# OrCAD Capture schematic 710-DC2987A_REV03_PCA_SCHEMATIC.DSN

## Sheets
1 PAGE 2
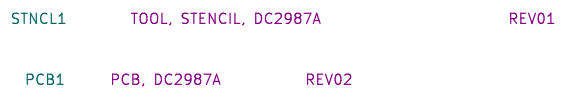
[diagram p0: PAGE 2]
2 LT3935JV: size Custom; company: 36V, 4A SYNCHRONOUS BUCK LED DRIVER
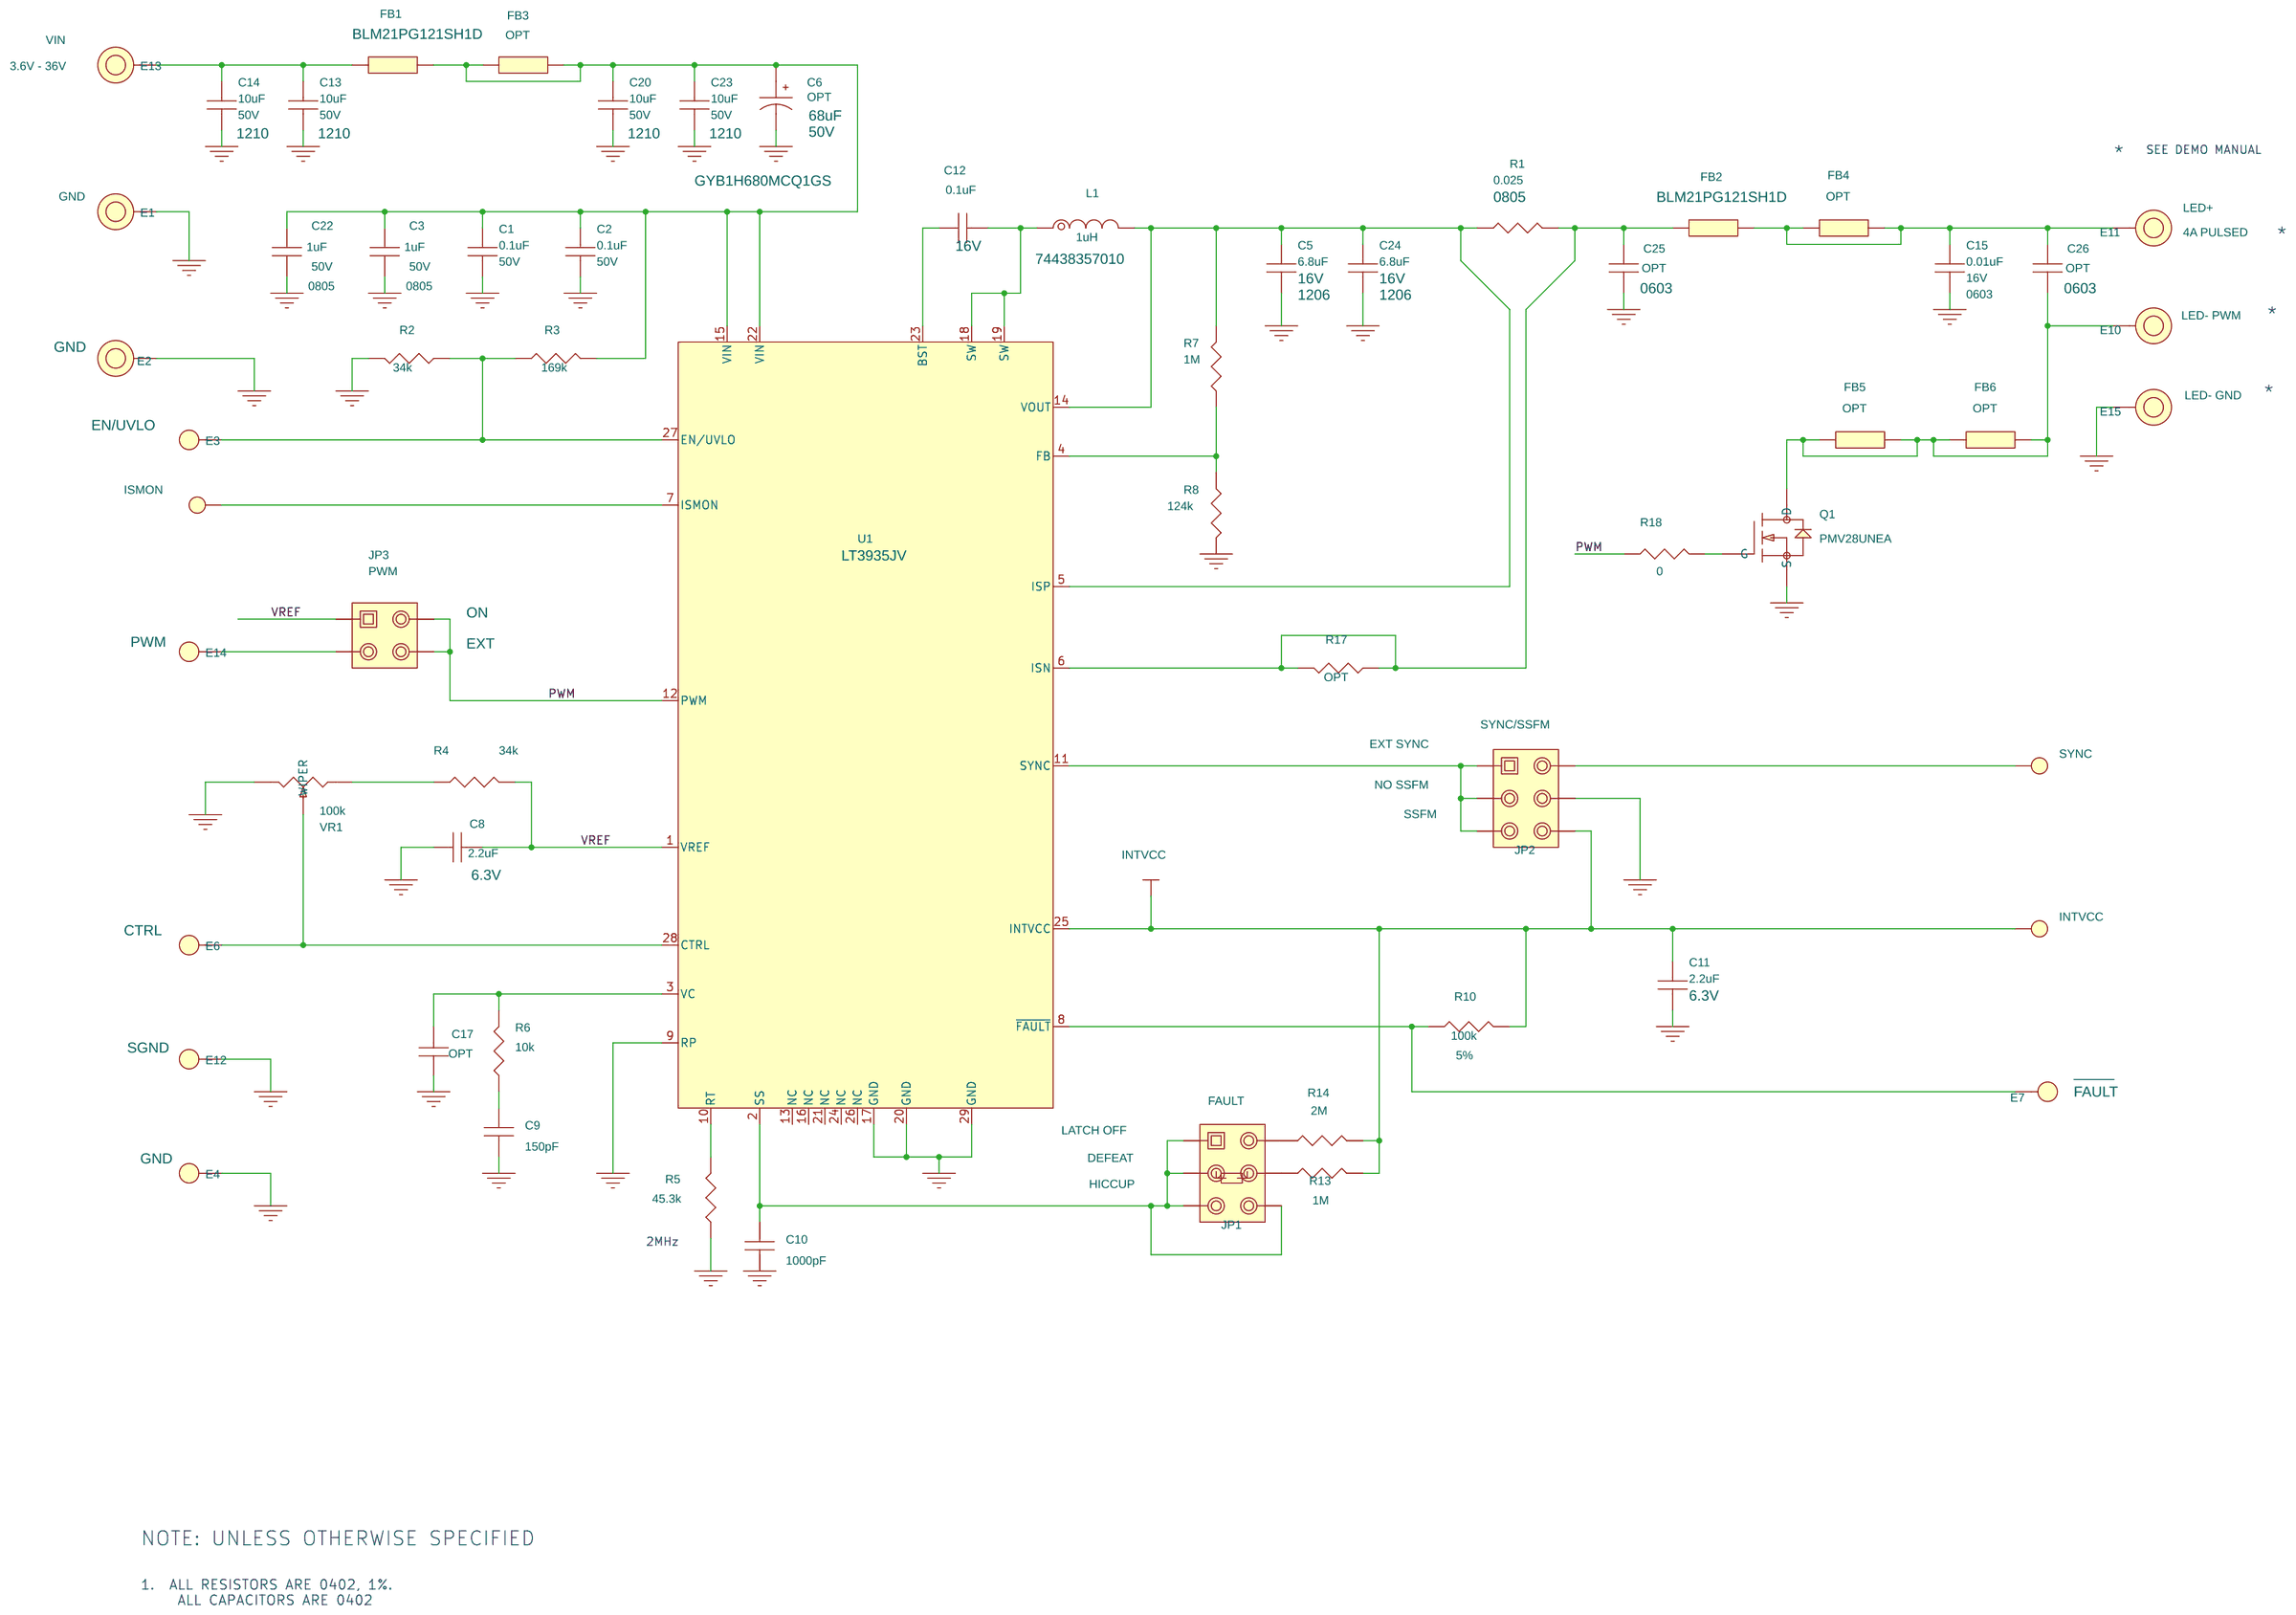
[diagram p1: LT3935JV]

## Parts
sheet LT3935JV
C1  0.1uF  [CC0402N]
C2  0.1uF  [CC0402N]
C3  1uF  [CC0805N]
C5  6.8uF  [CC1206N]
C6  OPT  [USER_8]
C8  2.2uF  [CC0402N]
C9  150pF  [CC0402N]
C10  1000pF  [CC0402N]
C11  2.2uF  [CC0402N]
C12  0.1uF  [CC0402N]
C13  10uF  [CC1210N]
C14  10uF  [CC1210N]
C15  0.01uF  [CC0603N]
C17  OPT  [CC0402N]
C20  10uF  [CC1210N]
C22  1uF  [CC0805N]
C23  10uF  [CC1210N]
C24  6.8uF  [CC1206N]
C25  OPT  [CC0603N]
C26  OPT  [CC0603N]
E1  TEST POINT  [MILLMAX2501]
E2  TEST POINT  [MILLMAX2501]
E3  TEST POINT  [MILLMAX2308]
E4  TEST POINT  [MILLMAX2308]
E6  TEST POINT  [MILLMAX2308]
E7  TEST POINT  [MILLMAX2308]
E10  TEST POINT  [MILLMAX2501]
E11  TEST POINT  [MILLMAX2501]
E12  TEST POINT  [MILLMAX2308]
E13  TEST POINT  [MILLMAX2501]
E14  TEST POINT  [MILLMAX2308]
E15  TEST POINT  [MILLMAX2501]
FB1  120 OHMS @ 100MHz  [IND0805N]
FB2  120 OHMS @ 100MHz  [IND0805N]
FB3  OPT  [IND0805N]
FB4  OPT  [IND0805N]
FB5  OPT  [IND0805N]
FB6  OPT  [IND0805N]
INTVCC  TEST PAD  [PADSTYLE8]
ISMON  TEST PAD  [PADSTYLE8]
JP1  HDR  [HD2X3-079]
JP2  HDR  [HD2X3-079]
JP3  HDR  [HD2X2-079]
L1  1uH  [WURTH-74438357010]
Q1  PMV28UNEA  [SOT23-3N]
R1  0.025  [CR0805N]
R2  34k  [CR0402N]
R3  169k  [CR0402N]
R4  34k  [CR0402N]
R5  45.3k  [CR0402N]
R6  10k  [CR0402N]
R7  1M  [CR0402N]
R8  124k  [CR0402N]
R10  100k  [CR0402N]
R13  1M  [CR0402N]
R14  2M  [CR0402N]
R17  OPT  [CR0402N]
R18  0  [CR0603N]
SYNC  TEST PAD  [PADSTYLE8]
U1  LT3935JV  [LTC-LQFN-28-XXXX]
VR1  100k  [BOURNES-3314J]
XJP1  SHUNT
XJP3  SHUNT
XJP6  SHUNT
sheet PAGE 2
PCB1  PCB, DC2987A
STNCL1  TOOL, STENCIL, DC2987A

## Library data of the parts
C1 C2 = CAP: CAP.,0.1uF,X7R,50V,10%,0402,AEC-Q200, NO SUBS. ALLOWED; CLASS: DISCRETE; Dielectric Type: X7R; FPLIST: CC0402N,CC0402L,CC0402M; Inventory Qty: 11376; Manufacturer: MURATA; Manufacturer PN: GCM155R71H104KE02D; PART_NUMBER: 150-2353; Package Size: 0402; Rated Voltage: 50V; Tolerance: 10%
C3 C22 = CAP: CAP.,1uF,X7R,50V,10%,0805,AEC-Q200,NO SUBS ALLOWED; CLASS: DISCRETE; Dielectric Type: X7R; FPLIST: CC0805N,CC0805L,CC0805M; Inventory Qty: 2980; Manufacturer: MURATA; Manufacturer PN: GCM21BR71H105KA03L; PART_NUMBER: 150-1209; Package Size: 0805; Rated Voltage: 50V; Temperature Coefficient: X7R; Tolerance: 10%
C5 C24 = CAP: CAP.,6.8uF,X7R,16V,10%,1206,AEC-Q200,NO SUBS ALLOWED; CLASS: DISCRETE; Dielectric Type: X7R; Inventory Qty: 0; Manufacturer: TDK; Manufacturer PN: CGA5L1X7R1C685K160AC; PART_NUMBER: 150-0936; Package Size: 1206; Rated Voltage: 16V; Tolerance: 10%
C6 = CAP_P_ALT: CAP.,OPTION,ALUM. ELECT.,SMD; CLASS: DISCRETE; FPLIST: USER_ASSIGNED,USER_8,USER_9,USER_10,USER_11,USER_12,USER_13,USER_14,CAP_OPT_6.3,CAP_OPT_8,CAP_OPT_10,CAP_OPT_12.5,CAP_OPT_13,CAP_OPT_16,CAP_OPT_18; MANU: GYB1H680MCQ1GS; OPT: 68uF; PART_NUMBER: 150-3568; Package Type: SMD; V: 50V
C8 C11 = CAP: CAP.,2.2uF,X5R,25V,10%,0402,AEC-Q200; 1ST PART FIELD: 6.3V; CLASS: DISCRETE; Dielectric Type: X5R; FPLIST: CC0402N,CC0402L,CC0402M; Inventory Qty: 0; Manufacturer: MURATA; Manufacturer PN: GRT155R61E225KE13D; PART_NUMBER: 150-2647; Package Size: 0402; Rated Voltage: 25V; Tolerance: 10%
C9 = CAP: CAP.,150pF,C0G/NP0,25V,5%,0402; CLASS: DISCRETE; Dielectric Type: C0G/NP0; FPLIST: CC0402N,CC0402L,CC0402M; Inventory Qty: 0; Manufacturer: AVX; Manufacturer PN: 04023A151JAT2A; PART_NUMBER: 150-2648; Package Size: 0402; Rated Voltage: 25V; Tolerance: 5%
C10 = CAP: CAP.,1000pF,X7R,25V,10%,0402; CLASS: DISCRETE; Dielectric Type: X7R; FPLIST: CC0402N,CC0402L,CC0402M; Inventory Qty: 46656; Manufacturer: AVX; Manufacturer PN: 04023C102KAT2A; PART_NUMBER: 150-2012; Package Size: 0402; Rated Voltage: 25V; Tolerance: 10%
C12 = CAP: CAP.,0.1uF,X7R,16V,10%,0402; CLASS: DISCRETE; Dielectric Type: X7R; FPLIST: CC0402N,CC0402L,CC0402M; Inventory Qty: 334081; Manufacturer: AVX; Manufacturer PN: 0402YC104KAT2A; PART_NUMBER: 150-2081; Package Size: 0402; Rated Voltage: 16V; Tolerance: 10%
C13 C14 C20 C23 = CAP: CAP.,10uF,X7S,50V,10%,1210,AEC-Q200, NO SUBS ALLOWED; CLASS: DISCRETE; Dielectric Type: X7S; FPLIST: CC1210N,CC1210L,CC1210M; Inventory Qty: 10880; Manufacturer: MURATA; Manufacturer PN: GCM32EC71H106KA03L; PART_NUMBER: 150-2354; Package Size: 1210; Rated Voltage: 50V; Tolerance: 10%
C15 = CAP: CAP.,0.01uF,X7R,16V,10%,0603; CLASS: DISCRETE; Dielectric Type: X7R; FPLIST: CC0603N,CC0603L,CC0603M; Inventory Qty: 67002; Manufacturer: AVX; Manufacturer PN: 0603YC103KAT2A; PART_NUMBER: 150-0038; Package Size: 0603; Rated Voltage: 16V; Tolerance: 10%
C17 = CAP: CAP., OPTION, 0402; CLASS: DISCRETE; FPLIST: CC0402N,CC0402L,CC0402M; PART_NUMBER: 150-3148; Package Size: 0402; Package Type: SMD
C25 C26 = CAP: CAP., OPTION, 0603; CLASS: DISCRETE; FPLIST: CC0603N,CC0603L,CC0603M; PART_NUMBER: 150-3038; Package Size: 0603; Package Type: SMD
E1 = TESTPOINT_.219_MILL-MAX_2501_A: TEST POINT,TURRET,0.094" MTG. HOLE,PCB 0.062" THK; CLASS: IO; Inventory Qty: 824926; Manufacturer: MILL-MAX; Manufacturer PN: 2501-2-00-80-00-00-07-0; PART_FIELD_01: GND; PART_NUMBER: 260-0003
E2 = TESTPOINT_.219_MILL-MAX_2501_A: TEST POINT,TURRET,0.094" MTG. HOLE,PCB 0.062" THK; CLASS: IO; FPLIST: MILLMAX2501,MILLMAX2501_ALT1; Inventory Qty: 824926; Manufacturer: MILL-MAX; Manufacturer PN: 2501-2-00-80-00-00-07-0; PART_FIELD_01: GND; PART_NUMBER: 260-0003
E3 = TEST_POINT_.156_MILL-MAX_2308: TEST POINT,TURRET,0.064" MTG. HOLE,PCB 0.062" THK; CLASS: IO; Inventory Qty: 1155860; Manufacturer: MILL-MAX; Manufacturer PN: 2308-2-00-80-00-00-07-0; PART_FIELD_1: EN/UVLO; PART_NUMBER: 260-0004
E4 = TEST_POINT_.156_MILL-MAX_2308: TEST POINT,TURRET,0.064" MTG. HOLE,PCB 0.062" THK; CLASS: IO; Inventory Qty: 1155860; Manufacturer: MILL-MAX; Manufacturer PN: 2308-2-00-80-00-00-07-0; PART_FIELD_1: GND; PART_NUMBER: 260-0004
E6 = TEST_POINT_.156_MILL-MAX_2308: TEST POINT,TURRET,0.064" MTG. HOLE,PCB 0.062" THK; CLASS: IO; Inventory Qty: 1155860; Manufacturer: MILL-MAX; Manufacturer PN: 2308-2-00-80-00-00-07-0; PART_FIELD_1: CTRL; PART_NUMBER: 260-0004
E7 = TEST_POINT_.156_MILL-MAX_2308: TEST POINT,TURRET,0.064" MTG. HOLE,PCB 0.062" THK; CLASS: IO; Inventory Qty: 1155860; Manufacturer: MILL-MAX; Manufacturer PN: 2308-2-00-80-00-00-07-0; PART_FIELD_1: FAULT; PART_FIELD_2: _____; PART_NUMBER: 260-0004
E10 = TESTPOINT_.219_MILL-MAX_2501_A: TEST POINT,TURRET,0.094" MTG. HOLE,PCB 0.062" THK; CLASS: IO; Inventory Qty: 824926; Manufacturer: MILL-MAX; Manufacturer PN: 2501-2-00-80-00-00-07-0; PART_FIELD_01: LED- PWM; PART_FIELD_02: GND; PART_NUMBER: 260-0003
E11 = TESTPOINT_.219_MILL-MAX_2501_A: TEST POINT,TURRET,0.094" MTG. HOLE,PCB 0.062" THK; CLASS: IO; Inventory Qty: 824926; Manufacturer: MILL-MAX; Manufacturer PN: 2501-2-00-80-00-00-07-0; PART_FIELD_01: LED+; PART_FIELD_02: 4A PULSED; PART_NUMBER: 260-0003
E12 = TEST_POINT_.156_MILL-MAX_2308: TEST POINT,TURRET,0.064" MTG. HOLE,PCB 0.062" THK; CLASS: IO; Inventory Qty: 1155860; Manufacturer: MILL-MAX; Manufacturer PN: 2308-2-00-80-00-00-07-0; PART_FIELD_1: SGND; PART_NUMBER: 260-0004
E13 = TESTPOINT_.219_MILL-MAX_2501_A: TEST POINT,TURRET,0.094" MTG. HOLE,PCB 0.062" THK; CLASS: IO; Inventory Qty: 824926; Manufacturer: MILL-MAX; Manufacturer PN: 2501-2-00-80-00-00-07-0; PART_FIELD_01: 3.6V - 36V; PART_FIELD_02: VIN; PART_NUMBER: 260-0003
E14 = TEST_POINT_.156_MILL-MAX_2308: TEST POINT,TURRET,0.064" MTG. HOLE,PCB 0.062" THK; CLASS: IO; Inventory Qty: 1155860; Manufacturer: MILL-MAX; Manufacturer PN: 2308-2-00-80-00-00-07-0; PART_FIELD_1: PWM; PART_NUMBER: 260-0004
E15 = TESTPOINT_.219_MILL-MAX_2501_A: TEST POINT,TURRET,0.094" MTG. HOLE,PCB 0.062" THK; CLASS: IO; Inventory Qty: 824926; Manufacturer: MILL-MAX; Manufacturer PN: 2501-2-00-80-00-00-07-0; PART_FIELD_01: LED- GND; PART_FIELD_02: GND; PART_NUMBER: 260-0003
FB1 FB2 = FERRITEBEAD_ALT1: IND.,120 OHMS @ 100MHz,FERRITE BEAD,25%,3A,30mOHM,0805,AEC-Q200; CLASS: DISCRETE; Inventory Qty: 0; Manufacturer: MURATA; Manufacturer PN: BLM21PG121SH1D; PART_NUMBER: 200-0402; Package Size: 0805; Tolerance: 25%
FB3-FB6 = FERRITEBEAD_ALT1: IND.,FERRITE BEAD,OPT,0805; CLASS: DISCRETE; FPLIST: IND0805N,IND0805L,IND0805M; PART_NUMBER: 200-0529; Package Size: 0805
INTVCC ISMON SYNC = PAD_STYLE_E: TESTPOINT, PCB COPPER FEATURE; CLASS: IO; FPLIST: PADSTYLE1,PADSTYLE2,PADSTYLE3,PADSTYLE4,PADSTYLE5,PADSTYLE6,PADSTYLE7,PADSTYLE8
JP1 = HDR2X3_ALT1: CONN.,HDR,MALE,2x3,2mm,VERT,ST,THT; 10th Part Field: DEFEAT; 11th Part Field: HICCUP; 13tht Part Field: FAULT; 9th Part Field: LATCH OFF; CLASS: IO; FPLIST: HD2X3-079,WURTH-62000621121; Inventory Qty: 17851; Manufacturer: WURTH ELEKTRONIK; Manufacturer PN: 62000621121; PART_NUMBER: 250-0483
JP2 = HDR2X3_ALT1: CONN.,HDR,MALE,2x3,2mm,VERT,ST,THT; 10th Part Field: NO SSFM; 11th Part Field: SSFM; 13tht Part Field: SYNC/SSFM; 9th Part Field: EXT SYNC; CLASS: IO; FPLIST: HD2X3-079,WURTH-62000621121; Inventory Qty: 17851; Manufacturer: WURTH ELEKTRONIK; Manufacturer PN: 62000621121; PART_NUMBER: 250-0483
JP3 = HDR2X2_ALT1: CONN.,HDR,MALE,2x2,2mm,VERT,ST,THT; 9th Part Field: PWM; CLASS: IO; Inventory Qty: 6124; Manufacturer: SULLINS CONNECTOR SOLUTIONS; Manufacturer PN: NRPN022PAEN-RC; PART_NUMBER: 250-0551; TEXT1: ON; TEXT2: EXT
L1 = IND_A: IND.,1uH,FIXED,+/-20%,7.4A,13.5mOHMS,; CLASS: DISCRETE; Inventory Qty: 0; Manufacturer: WURTH ELEKTRONIK; Manufacturer PN: 74438357010; PART_NUMBER: 200-0808; Tolerance: +/-20%
Q1 = 3P_N-CH_TYPE1A: XSTR.,MOSFET,N-CH,20V,4.7A,SOT23-3; CLASS: DISCRETE; Inventory Qty: 0; Manufacturer: NEXPERIA; Manufacturer PN: PMV28UNEAR; PART_NUMBER: 240-0575; Package Type: SOT23-3; Rated Voltage: 20V
R1 = RES: RES.,0.025 OHMS,1%,1/2W,0805,SHORT-SIDE TERM.,METAL,AEC-Q200; CLASS: DISCRETE; Inventory Qty: 0; Manufacturer: SUSUMU; Manufacturer PN: KRL1220E-M-R025-F-T1; PART_NUMBER: 100-1736; Package Size: 0805,SHORT-SIDE TERM.; Rated Power: 1/2W; Temperature Coefficient: +/-50ppm; Tolerance: 1%; size: 0805
R2 R4 = RES: RES.,34k OHMS,1%,1/16W,0402; 3rd Part Field: 0402; CLASS: DISCRETE; FPLIST: CR0402N,CR0402L,CR0402M; Inventory Qty: 10625; Manufacturer: BOURNS; Manufacturer PN: CR0402-FX-3402GLF; PART_NUMBER: 100-2567; Package Size: 0402; Rated Power: 1/16W; Temperature Coefficient: 100ppm; Tolerance: 1%
R3 = RES: RES.,169k OHMS,1%,1/16W,0402,AEC-Q200; 3rd Part Field: 0402; 4th Part Field: MFG; 5th Part Field: Part#; CLASS: DISCRETE; FPLIST: CR0402N,CR0402L,CR0402M; Inventory Qty: 9964; Manufacturer: VISHAY; Manufacturer PN: CRCW0402169KFKED; PART_NUMBER: 100-0708; Package Size: 0402; Rated Power: 1/16W; Temperature Coefficient: 100ppm; Tolerance: 1%
R5 = RES: RES.,45.3k OHMS,1%,1/16W,0402,AEC-Q200; 3rd Part Field: 0402; CLASS: DISCRETE; FPLIST: CR0402N,CR0402L,CR0402M; Inventory Qty: 39944; Manufacturer: VISHAY; Manufacturer PN: CRCW040245K3FKED; PART_NUMBER: 100-0662; Package Size: 0402; Rated Power: 1/16W; Temperature Coefficient: +/-100PPM; Tolerance: 1%
R6 = RES: RES.,10k OHMS,1%,1/16W,0402,AEC-Q200; 3rd Part Field: 0402; 6th Part Field: 5%; CLASS: DISCRETE; FPLIST: CR0402N,CR0402L,CR0402M; Inventory Qty: 76726; Manufacturer: VISHAY; Manufacturer PN: CRCW040210K0FKED; PART_NUMBER: 100-2545; Package Size: 0402; Rated Power: 1/16W; Temperature Coefficient: 100ppm/C; Tolerance: 1%
R7 R13 = RES: RES.,1M OHMS,1%,1/16W,0402,AEC-Q200; 3rd Part Field: 0402; CLASS: DISCRETE; FPLIST: CR0402N,CR0402L,CR0402M; Inventory Qty: 86572; Manufacturer: STACKPOLE ELECTRONICS, INC.; Manufacturer PN: RMCF0402FT1M00; PART_NUMBER: 100-2457; Package Size: 0402; Rated Power: 1/16W; Temperature Coefficient: 100ppm; Tolerance: 1%
R8 = RES: RES.,124k OHMS,1%,1/16W,0402,AEC-Q200; CLASS: DISCRETE; FPLIST: CR0402N,CR0402L,CR0402M; Inventory Qty: 10300; Manufacturer: NIC; Manufacturer PN: NRC04F1243TRF; PART_NUMBER: 100-2868; Package Size: 0402; Rated Power: 1/16W; Temperature Coefficient: 100PPM; Tolerance: 1%
R10 = RES: RES.,100k OHMS,5%,1/16W,0402,AEC-Q200; 3rd Part Field: 0402; 6th Part Field: 5%; CLASS: DISCRETE; FPLIST: CR0402N,CR0402L,CR0402M; Inventory Qty: 59612; Manufacturer: NIC; Manufacturer PN: NRC04J104TRF; PART_NUMBER: 100-0359; Package Size: 0402; Rated Power: 1/16W; Temperature Coefficient: 200ppm/C; Tolerance: 5%
R14 = RES: RES.,2M OHMS,1%,1/16W,0402,AEC-Q200; 3rd Part Field: 0402; CLASS: DISCRETE; FPLIST: CR0402N,CR0402L,CR0402M; Inventory Qty: 19028; Manufacturer: VISHAY; Manufacturer PN: CRCW04022M00FKED; PART_NUMBER: 100-2884; Package Size: 0402; Rated Power: 1/16W; Temperature Coefficient: 100ppm; Tolerance: 1%
R17 = RES: RES., OPTION, 0402; 3rd Part Field: 0402; CLASS: DISCRETE; FPLIST: CR0402N,CR0402L,CR0402M; PART_NUMBER: 100-0357; Package Size: 0402
R18 = RES: RES.,0 OHM,1/10W,0603,AEC-Q200; CLASS: DISCRETE; FPLIST: CR0603N,CR0603L,CR0603M; Inventory Qty: 696291; Manufacturer: VISHAY; Manufacturer PN: CRCW06030000Z0EA; PART_NUMBER: 100-0009; Package Size: 0603; Rated Power: 1/10W
U1 = LT3935-LQFN: IC,36V,4A,SYNC. BUCK LED DRIVER,LQFN-28; CLASS: IC; Inventory Qty: 0; Manufacturer: ANALOG DEVICES; Manufacturer PN: LT3935JV#PBF; PART_NUMBER: LT3935JV#PBF; Package Size: 5MMX4MM; Package Type: LQFN-28
VR1 = TRIMPOT: RES.,100k OHMS,20%,1/4W,SMD 4mm SQ,1-TURN,TOP ADJ.,TRIMPOT; CLASS: DISCRETE; Inventory Qty: 12283; Manufacturer: BOURNS; Manufacturer PN: 3314J-1-104E; PART_NUMBER: 103-0025; Package Size: SMD 4mm SQ; Rated Power: 1/4W; Temperature Coefficient: 100ppm; Tolerance: 20%
XJP1 XJP3 XJP6 = SHUNT_2MM_C: CONN.,SHUNT,FEMALE,2 POS,2mm; CLASS: IO; Inventory Qty: 66518; Manufacturer: Wurth Elektronik; Manufacturer PN: 60800213421; PART_NUMBER: 250-0485
PCB1 = BLANK_PCB_PART: BOM Notes: REV02; CLASS: DISCRETE; Inventory Qty: 0; Manufacturer: ADI APPROVED SUPPLIER; Manufacturer PN: 600-DC2987A; PART_NUMBER: 600-DC2987A
STNCL1 = BLANK_STENCIL_PART: BOM Notes: REV01; CLASS: DISCRETE; Inventory Qty: 0; Manufacturer: ADI APPROVED SUPPLIER; Manufacturer PN: 830-DC2987A; PART_NUMBER: 830-DC2987A

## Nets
GND: C1.2 C2.2 C3.2 C5.2 C6.2 C8.1 C9.2 C10.2 C11.2 C13.2 C14.2 C15.2 C17.1 C20.2 C22.2 C23.2 C24.2 C25.2 E1.1 E2.1 E4.1(A) E12.1(A) E15.1 JP2.4 Q1.2(S) R2.2 R5.1 R8.1 U1.9(RP) U1.17(GND) U1.20(GND) U1.29(GND) VR1.1
INTVCC: C11.1 INTVCC.1(TP) JP2.6 R10.2 R13.2 R14.2 U1.25(INTVCC)
PWM: JP3.2 JP3.4 R18.1 U1.12(PWM)
VREF: C8.2 JP3.1 R4.2 U1.1(VREF)
N17139358: E3.1(A) R2.1 R3.1 U1.27(EN/UVLO)
N17139755: ISMON.1(TP) U1.7(ISMON)
N17140374: C1.1 C2.1 C3.1 C6.1 C20.1 C22.1 C23.1 FB1.2 FB3.1 FB3.2 R3.2 U1.15(VIN) U1.22(VIN)
N17146129: C5.1 C24.1 L1.2 R1.2 R7.2 U1.5(ISP) U1.14(VOUT)
N17149786: C25.1 FB2.1 R1.1 R17.1 R17.2 U1.6(ISN)
N17166636: C10.1 JP1.1 JP1.3 JP1.5 JP1.6 U1.2(SS)
N17169589: E7.1(A) R10.1 U1.8(~{FAULT})
N17183461: C12.2 L1.1 U1.18(SW) U1.19(SW)
N17186412: R7.1 R8.2 U1.4(FB)
N17458799: C9.1 R6.1
N17458801: C17.2 R6.2 U1.3(VC)
N17464964: E6.1(A) U1.28(CTRL) VR1.2(WIPER)
N17505690: C12.1 U1.23(BST)
N17508003: C13.1 C14.1 E13.1 FB1.1
N17529258: C15.1 C26.1 E11.1 FB2.2 FB4.1 FB4.2
N17539991: JP2.1 JP2.3 JP2.5 U1.11(SYNC)
N17540036: JP2.2 SYNC.1(TP)
N17546574: C26.2 E10.1 FB5.1 FB5.2 FB6.1 FB6.2 Q1.3(D)
N17602012: R5.2 U1.10(RT)
N17646957: E14.1(A) JP3.3
N17650112: Q1.1(G) R18.2
N17651510: R4.1 VR1.3
N17675142: JP1.2 R14.1
N17675143: JP1.4 R13.1

Not connected (* = marked no-connect by the designer): U1 13(NC) 16(NC) 21(NC) 24(NC) 26(NC)

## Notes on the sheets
sheet 2
- *
- SEE DEMO MANUAL
- *
- *
- *
- 2MHz
- NOTE: UNLESS OTHERWISE SPECIFIED
- 1.  ALL RESISTORS ARE 0402, 1%.
       ALL CAPACITORS ARE 0402
